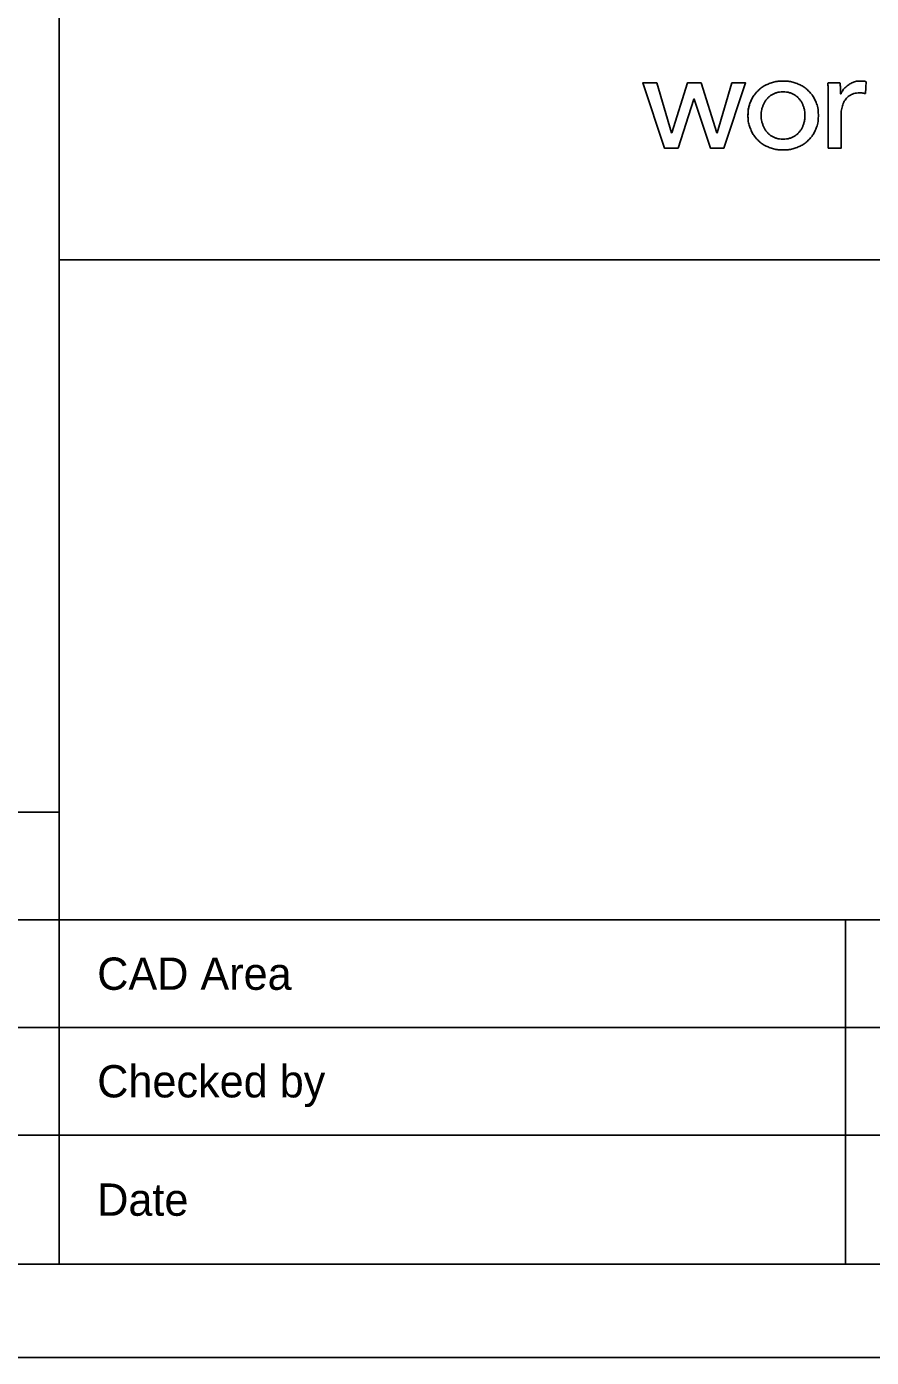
# Model space of a CAD drawing. Extents: x 613360 to 613780, y 4825621 to 4825911.
# Drawn here: x 613709.87 to 613733.41, y 4825620.91 to 4825658.01 of the extents above; entities that cross this region are included whole.
import ezdxf

# ---------------------------------------------------------------- set-up
doc = ezdxf.new("R2010")
doc.units = 0
for name, color, linetype in [('G-ANNO-TTLB-TEXT', 7, 'Continuous'), ('G-TTLB-LOGO', 7, 'Continuous'), ('G-TTLB-OTLN', 7, 'Continuous'), ('G-TTLB-OTLN-PB', 7, 'Continuous')]:
    doc.layers.add(name, color=color, linetype=linetype)

msp = doc.modelspace()

# ---------------------------------------------------------------- linework, layer by layer
at = {"layer": 'G-TTLB-LOGO'}
for p, q in [((613727.644, 4825654.626), (613727.038, 4825656.446)), ((613727.038, 4825656.446), (613727.429, 4825656.446)), ((613727.429, 4825656.446), (613727.84, 4825655.056)), ((613727.848, 4825655.056), (613728.282, 4825656.446)), ((613728.282, 4825656.446), (613728.662, 4825656.446)), ((613728.662, 4825656.446), (613729.104, 4825655.056)), ((613729.112, 4825655.056), (613729.523, 4825656.446)), ((613729.903, 4825656.446), (613729.3, 4825654.626)), ((613729.523, 4825656.446), (613729.903, 4825656.446)), ((613728.466, 4825655.993), (613728.021, 4825654.626)), ((613728.474, 4825655.993), (613728.466, 4825655.993)), ((613728.923, 4825654.626), (613728.474, 4825655.993)), ((613727.84, 4825655.056), (613727.848, 4825655.056)), ((613729.104, 4825655.056), (613729.112, 4825655.056)), ((613728.021, 4825654.626), (613727.644, 4825654.626)), ((613729.3, 4825654.626), (613728.923, 4825654.626))]:
    msp.add_line(p, q, dxfattribs=at)
msp.add_lwpolyline([(613727.429, 4825656.446), (613727.84, 4825655.056), (613727.848, 4825655.056), (613728.282, 4825656.446), (613728.662, 4825656.446), (613729.104, 4825655.056), (613729.112, 4825655.056), (613729.523, 4825656.446), (613729.903, 4825656.446), (613729.3, 4825654.626), (613728.923, 4825654.626), (613728.474, 4825655.993), (613728.466, 4825655.993), (613728.021, 4825654.626), (613727.644, 4825654.626), (613727.038, 4825656.446), (613727.429, 4825656.446)], dxfattribs=at)
for points in [[(613731.933, 4825655.54), (613731.933, 4825655.399), (613731.908, 4825655.269), (613731.859, 4825655.152), (613731.808, 4825655.034), (613731.739, 4825654.932), (613731.651, 4825654.846), (613731.563, 4825654.761), (613731.458, 4825654.694), (613731.338, 4825654.647), (613731.218, 4825654.599), (613731.088, 4825654.576), (613730.95, 4825654.576), (613730.812, 4825654.576), (613730.683, 4825654.599), (613730.562, 4825654.647), (613730.442, 4825654.694), (613730.338, 4825654.761), (613730.251, 4825654.846), (613730.164, 4825654.932), (613730.095, 4825655.034), (613730.046, 4825655.152), (613729.996, 4825655.269), (613729.971, 4825655.399), (613729.971, 4825655.54), (613729.971, 4825655.681), (613729.996, 4825655.809), (613730.046, 4825655.926), (613730.095, 4825656.042), (613730.164, 4825656.143), (613730.251, 4825656.227), (613730.338, 4825656.312), (613730.442, 4825656.378), (613730.562, 4825656.425), (613730.683, 4825656.472), (613730.812, 4825656.496), (613730.95, 4825656.496), (613731.088, 4825656.496), (613731.218, 4825656.472), (613731.338, 4825656.425), (613731.458, 4825656.378), (613731.563, 4825656.312), (613731.651, 4825656.227), (613731.739, 4825656.143), (613731.808, 4825656.042), (613731.859, 4825655.926), (613731.908, 4825655.809), (613731.933, 4825655.681), (613731.933, 4825655.54)], [(613729.993, 4825655.76), (613730.006, 4825655.818), (613730.023, 4825655.873), (613730.046, 4825655.926), (613730.095, 4825656.042), (613730.164, 4825656.143), (613730.251, 4825656.227), (613730.338, 4825656.312), (613730.442, 4825656.378), (613730.562, 4825656.425), (613730.683, 4825656.472), (613730.812, 4825656.496), (613730.95, 4825656.496), (613731.088, 4825656.496), (613731.218, 4825656.472), (613731.338, 4825656.425), (613731.458, 4825656.378), (613731.563, 4825656.312), (613731.651, 4825656.227), (613731.739, 4825656.143), (613731.808, 4825656.042), (613731.859, 4825655.926), (613731.908, 4825655.809), (613731.933, 4825655.681), (613731.933, 4825655.54)], [(613732.205, 4825656.242), (613732.203, 4825656.32), (613732.199, 4825656.387), (613732.194, 4825656.446), (613732.194, 4825656.446), (613732.536, 4825656.446), (613732.536, 4825656.446), (613732.541, 4825656.4), (613732.545, 4825656.347), (613732.547, 4825656.287), (613732.55, 4825656.227), (613732.551, 4825656.177), (613732.551, 4825656.139), (613732.551, 4825656.139), (613732.563, 4825656.139), (613732.563, 4825656.139), (613732.614, 4825656.246), (613732.689, 4825656.333), (613732.787, 4825656.398), (613732.886, 4825656.464), (613732.997, 4825656.496), (613733.12, 4825656.496), (613733.176, 4825656.496), (613733.223, 4825656.491), (613733.262, 4825656.481), (613733.262, 4825656.481), (613733.246, 4825656.147), (613733.246, 4825656.147), (613733.195, 4825656.159), (613733.14, 4825656.166), (613733.081, 4825656.166), (613732.994, 4825656.166), (613732.919, 4825656.15), (613732.855, 4825656.118), (613732.79, 4825656.086), (613732.737, 4825656.043), (613732.695, 4825655.989), (613732.653, 4825655.935), (613732.622, 4825655.873), (613732.601, 4825655.803), (613732.58, 4825655.732), (613732.57, 4825655.659), (613732.57, 4825655.582), (613732.57, 4825655.582), (613732.57, 4825654.626), (613732.57, 4825654.626), (613732.57, 4825654.626), (613732.209, 4825654.626), (613732.209, 4825654.626), (613732.209, 4825654.626), (613732.209, 4825656.054), (613732.209, 4825656.054), (613732.209, 4825656.103), (613732.208, 4825656.166), (613732.205, 4825656.242)], [(613732.205, 4825656.242), (613732.203, 4825656.32), (613732.199, 4825656.387), (613732.194, 4825656.446), (613732.194, 4825656.446), (613732.536, 4825656.446), (613732.536, 4825656.446), (613732.541, 4825656.4), (613732.545, 4825656.347), (613732.547, 4825656.287), (613732.55, 4825656.227), (613732.551, 4825656.177), (613732.551, 4825656.139), (613732.551, 4825656.139), (613732.563, 4825656.139), (613732.563, 4825656.139), (613732.614, 4825656.246), (613732.689, 4825656.333), (613732.787, 4825656.398), (613732.886, 4825656.464), (613732.997, 4825656.496), (613733.12, 4825656.496), (613733.176, 4825656.496), (613733.223, 4825656.491), (613733.262, 4825656.481), (613733.262, 4825656.481), (613733.246, 4825656.147), (613733.246, 4825656.147), (613733.195, 4825656.159), (613733.14, 4825656.166), (613733.081, 4825656.166), (613732.994, 4825656.166), (613732.919, 4825656.15), (613732.855, 4825656.118), (613732.79, 4825656.086), (613732.737, 4825656.043), (613732.695, 4825655.989), (613732.653, 4825655.935), (613732.622, 4825655.873), (613732.601, 4825655.803), (613732.58, 4825655.732), (613732.57, 4825655.659), (613732.57, 4825655.582), (613732.57, 4825655.582), (613732.57, 4825654.626), (613732.57, 4825654.626), (613732.57, 4825654.626), (613732.209, 4825654.626), (613732.209, 4825654.626), (613732.209, 4825654.626), (613732.209, 4825656.054), (613732.209, 4825656.054), (613732.209, 4825656.103), (613732.208, 4825656.166), (613732.205, 4825656.242)], [(613731.557, 4825655.538), (613731.557, 4825655.624), (613731.544, 4825655.707), (613731.517, 4825655.787), (613731.49, 4825655.866), (613731.45, 4825655.935), (613731.399, 4825655.995), (613731.348, 4825656.056), (613731.284, 4825656.103), (613731.208, 4825656.139), (613731.133, 4825656.175), (613731.046, 4825656.193), (613730.948, 4825656.193), (613730.851, 4825656.193), (613730.764, 4825656.175), (613730.688, 4825656.139), (613730.612, 4825656.103), (613730.549, 4825656.056), (613730.497, 4825655.995), (613730.446, 4825655.935), (613730.407, 4825655.866), (613730.38, 4825655.787), (613730.353, 4825655.707), (613730.34, 4825655.624), (613730.34, 4825655.538), (613730.34, 4825655.451), (613730.353, 4825655.368), (613730.38, 4825655.289), (613730.407, 4825655.21), (613730.446, 4825655.139), (613730.497, 4825655.078), (613730.549, 4825655.017), (613730.612, 4825654.968), (613730.688, 4825654.933), (613730.764, 4825654.897), (613730.851, 4825654.879), (613730.948, 4825654.879), (613731.046, 4825654.879), (613731.133, 4825654.897), (613731.208, 4825654.933), (613731.284, 4825654.968), (613731.348, 4825655.017), (613731.399, 4825655.078), (613731.45, 4825655.139), (613731.49, 4825655.21), (613731.517, 4825655.289), (613731.544, 4825655.368), (613731.557, 4825655.451), (613731.557, 4825655.538)], [(613731.557, 4825655.538), (613731.557, 4825655.624), (613731.544, 4825655.707), (613731.517, 4825655.787), (613731.49, 4825655.866), (613731.45, 4825655.935), (613731.399, 4825655.995), (613731.348, 4825656.056), (613731.284, 4825656.103), (613731.208, 4825656.139), (613731.133, 4825656.175), (613731.046, 4825656.193), (613730.948, 4825656.193), (613730.851, 4825656.193), (613730.764, 4825656.175), (613730.688, 4825656.139), (613730.612, 4825656.103), (613730.549, 4825656.056), (613730.497, 4825655.995), (613730.446, 4825655.935), (613730.407, 4825655.866), (613730.38, 4825655.787), (613730.353, 4825655.707), (613730.34, 4825655.624), (613730.34, 4825655.538), (613730.34, 4825655.451), (613730.353, 4825655.368), (613730.38, 4825655.289), (613730.407, 4825655.21), (613730.446, 4825655.139), (613730.497, 4825655.078), (613730.549, 4825655.017), (613730.612, 4825654.968), (613730.688, 4825654.933), (613730.764, 4825654.897), (613730.851, 4825654.879), (613730.948, 4825654.879), (613731.046, 4825654.879), (613731.133, 4825654.897), (613731.208, 4825654.933), (613731.284, 4825654.968), (613731.348, 4825655.017), (613731.399, 4825655.078), (613731.45, 4825655.139), (613731.49, 4825655.21), (613731.517, 4825655.289), (613731.544, 4825655.368), (613731.557, 4825655.451), (613731.557, 4825655.538)], [(613731.933, 4825655.54), (613731.933, 4825655.399), (613731.908, 4825655.269), (613731.859, 4825655.152), (613731.808, 4825655.034), (613731.739, 4825654.932), (613731.651, 4825654.846), (613731.563, 4825654.761), (613731.458, 4825654.694), (613731.338, 4825654.647), (613731.218, 4825654.599), (613731.088, 4825654.576), (613730.95, 4825654.576), (613730.812, 4825654.576), (613730.683, 4825654.599), (613730.562, 4825654.647), (613730.442, 4825654.694), (613730.338, 4825654.761), (613730.251, 4825654.846), (613730.164, 4825654.932), (613730.095, 4825655.034), (613730.046, 4825655.152), (613729.996, 4825655.269), (613729.971, 4825655.399), (613729.971, 4825655.54), (613729.971, 4825655.617), (613729.978, 4825655.69), (613729.993, 4825655.76)]]:
    msp.add_open_spline(points, degree=3, dxfattribs=at)
at = {"layer": 'G-TTLB-OTLN'}
for p, q in [((613710.777, 4825623.508), (613710.777, 4825815.929)), ((613774.178, 4825651.507), (613710.777, 4825651.507)), ((613380.085, 4825636.108), (613710.777, 4825636.108)), ((613380.086, 4825633.107), (613774.178, 4825633.107)), ((613732.691, 4825623.508), (613732.691, 4825633.108)), ((613380.086, 4825630.107), (613749.425, 4825630.107)), ((613380.086, 4825627.107), (613749.425, 4825627.107))]:
    msp.add_line(p, q, dxfattribs=at)
msp.add_lwpolyline([(613380.085, 4825892.077), (613774.178, 4825892.077), (613774.178, 4825623.508), (613380.085, 4825623.508)], close=True, dxfattribs=at)
at = {"layer": 'G-TTLB-OTLN-PB'}
msp.add_lwpolyline([(613359.578, 4825620.908), (613780.27, 4825620.908), (613780.27, 4825894.677), (613359.578, 4825894.677)], close=True, dxfattribs=at)

# ---------------------------------------------------------------- texts
at = {"layer": 'G-ANNO-TTLB-TEXT'}
for s, p in [('CAD Area', (613711.837, 4825631.157)), ('Checked by', (613711.837, 4825628.157)), ('Date', (613711.837, 4825624.857))]:
    msp.add_text(s, height=0.9, dxfattribs=at).set_placement(p)

doc.saveas('drawing.dxf')
